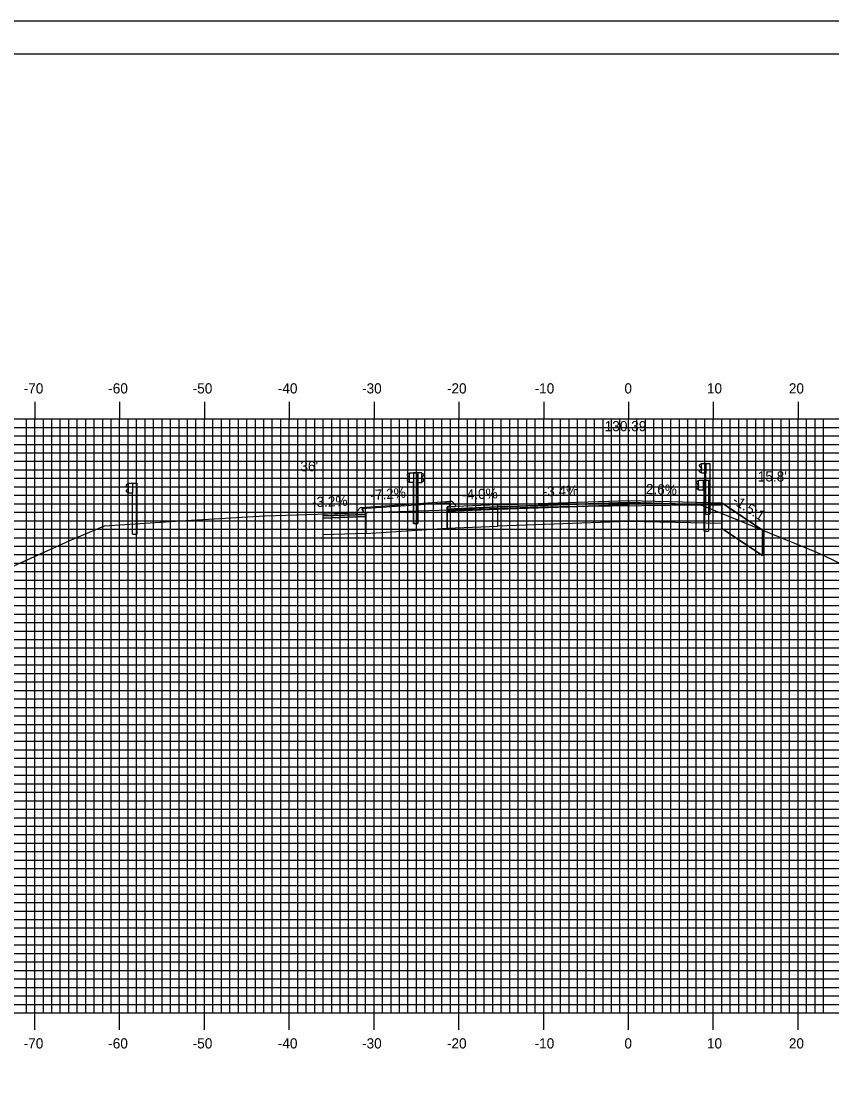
# Model space of a CAD drawing. Extents: x 859078 to 859421, y 364765 to 364985.
# Drawn here: x 859171.7 to 859267.3, y 364860.7 to 364985.2 of the extents above; entities that cross this region are included whole.
import ezdxf

# ---------------------------------------------------------------- set-up
doc = ezdxf.new("R2010")
doc.units = 0
for name, color, linetype in [('ANNOTATION', 7, 'Continuous'), ('BORDER', 7, 'Continuous'), ('D_Curb_Type_3M2_Lt', 7, 'Continuous'), ('D_Curb_Type_3M2_Rt', 7, 'Continuous'), ('D_Guardrail_Beam_Rt', 7, 'Continuous'), ('D_Roadway_Centerline_Text', 7, 'Continuous'), ('D_Roadway_Edge_Shoulder', 7, 'Continuous'), ('D_Roadway_Edge_TW', 7, 'Continuous'), ('D_Roadway_FinishedGrade', 7, 'Continuous'), ('D_Roadway_Pavement', 7, 'Continuous'), ('D_Roadway_SubGrade', 7, 'Continuous'), ('D_Text_Standard', 7, 'Continuous'), ('H_V ANNOTATION', 7, 'Continuous'), ('M_Guardrail', 7, 'Continuous'), ('M_Roadway_Centerline', 7, 'Continuous'), ('MAJOR', 7, 'Continuous'), ('MINOR', 7, 'Continuous'), ('PATTERNING', 7, 'Continuous'), ('PLOT BOUNDARY', 7, 'Continuous'), ('S_Roadway_Centerline', 7, 'Continuous')]:
    doc.layers.add(name, color=color, linetype=linetype)

msp = doc.modelspace()

# ---------------------------------------------------------------- linework, layer by layer
at = {"layer": 'BORDER'}
msp.add_lwpolyline([(859093.76, 364771.3), (859413.76, 364771.3), (859413.76, 364981.3), (859093.76, 364981.3)], close=True, dxfattribs=at)
at = {"layer": 'D_Curb_Type_3M2_Lt'}
for p, q in [((859222.47, 364928.59), (859222.47, 364928.59)), ((859222.33, 364928.46), (859222.22, 364927.97)), ((859222.22, 364927.97), (859222.97, 364927.97)), ((859222.97, 364928.13), (859222.62, 364928.53)), ((859222.97, 364927.97), (859222.97, 364928.13))]:
    msp.add_line(p, q, dxfattribs=at)
msp.add_arc((859222.49, 364928.42), 0.167, 41.387, 167.6648, dxfattribs=at)
at = {"layer": 'D_Curb_Type_3M2_Rt'}
for p, q in [((859211.37, 364927.41), (859211.73, 364927.81)), ((859211.37, 364927.24), (859211.37, 364927.41)), ((859212.01, 364927.74), (859212.12, 364927.24)), ((859212.12, 364927.24), (859211.37, 364927.24))]:
    msp.add_line(p, q, dxfattribs=at)
msp.add_arc((859211.85, 364927.7), 0.167, 12.3352, 138.613, dxfattribs=at)
at = {"layer": 'D_Guardrail_Beam_Rt'}
for p, q in [((859251.63, 364931.06), (859252.32, 364931.06)), ((859251.63, 364929.89), (859251.63, 364931.06)), ((859252.15, 364931.06), (859252.15, 364929.89)), ((859252.26, 364931.06), (859252.26, 364929.89)), ((859252.32, 364931.06), (859252.79, 364931.06)), ((859252.32, 364931.06), (859252.32, 364929.89)), ((859252.79, 364931.06), (859252.79, 364925.06)), ((859251.54, 364930.96), (859251.4, 364930.86)), ((859251.4, 364930.71), (859251.59, 364930.58)), ((859251.59, 364930.38), (859251.4, 364930.24)), ((859251.4, 364930.1), (859251.54, 364930)), ((859251.63, 364930.98), (859251.56, 364930.96)), ((859251.56, 364929.99), (859251.63, 364929.98)), ((859251.63, 364930.51), (859251.63, 364930.44)), ((859252.32, 364929.89), (859251.63, 364929.89)), ((859252.3, 364925.06), (859252.3, 364929.89)), ((859252.3, 364925.06), (859252.79, 364925.06))]:
    msp.add_line(p, q, dxfattribs=at)
for centre, major_axis, start_param, end_param in [((859251.45, 364930.79), (-0.0877, 0), 5.323254, 7.243116), ((859251.45, 364930.17), (-0.0877, 0), 5.323254, 7.243116), ((859251.56, 364930.92), (-0.0417, 0), 4.907132, 5.323254), ((859251.56, 364930.03), (-0.0417, 0), 0.959931, 1.376053), ((859251.55, 364930.51), (0.0789, 0), 0, 0.959931), ((859251.55, 364930.44), (0.0789, 0), 5.323254, 6.283185)]:
    msp.add_ellipse(centre, major_axis=major_axis, ratio=0.995501, start_param=start_param, end_param=end_param, dxfattribs=at)
at = {"layer": 'D_Roadway_Edge_Shoulder'}
for points in [[(859243.36, 364928.69), (859251.36, 364928.48), (859251.36, 364928.48), (859254.36, 364928.4), (859254.36, 364928.15), (859243.36, 364928.44)], [(859227.97, 364928.17), (859222.97, 364927.97), (859221.97, 364927.93), (859221.97, 364927.68), (859227.97, 364927.92)], [(859207.37, 364927.12), (859211.37, 364927.24), (859212.37, 364927.28), (859212.37, 364927.03), (859207.37, 364926.87)]]:
    msp.add_lwpolyline(points, close=True, dxfattribs=at)
at = {"layer": 'D_Roadway_Edge_TW'}
msp.add_lwpolyline([(859227.97, 364928.17), (859243.36, 364928.69), (859243.36, 364928.44), (859227.97, 364927.92)], close=True, dxfattribs=at)
at = {"layer": 'D_Roadway_FinishedGrade'}
msp.add_line((859254.36, 364928.4), (859254.36, 364925.4), dxfattribs=at)
for points in [[(859211.89, 364927.86), (859222.45, 364928.59)], [(859254.36, 364928.4), (859255.86, 364927.4), (859259.16, 364925.2)], [(859259.16, 364925.2), (859259.16, 364922.2), (859254.36, 364925.4)]]:
    msp.add_lwpolyline(points, dxfattribs=at)
at = {"layer": 'D_Roadway_Pavement'}
for points in [[(859227.97, 364927.92), (859221.97, 364927.68), (859221.97, 364927.43), (859227.97, 364927.67)], [(859227.97, 364927.92), (859243.36, 364928.44), (859243.36, 364928.19), (859227.97, 364927.67)], [(859207.37, 364926.87), (859212.37, 364927.03), (859212.37, 364926.78), (859207.37, 364926.62)]]:
    msp.add_lwpolyline(points, close=True, dxfattribs=at)
msp.add_lwpolyline([(859243.36, 364928.44), (859243.36, 364928.19)], dxfattribs=at)
msp.add_lwpolyline([(859243.36, 364928.44), (859243.36, 364928.19)], dxfattribs=at)
at = {"layer": 'D_Roadway_SubGrade'}
for points in [[(859212.37, 364927.28), (859212.37, 364924.78), (859221.97, 364925.43), (859221.97, 364927.43), (859221.97, 364927.68), (859221.97, 364927.93), (859222.21, 364927.94), (859222.32, 364928.41), (859211.9, 364927.7), (859212.12, 364927.27)], [(859227.97, 364927.67), (859221.97, 364927.43), (859221.97, 364927.68), (859221.97, 364925.43), (859227.97, 364925.67)], [(859227.97, 364927.67), (859243.36, 364928.19), (859243.36, 364926.19), (859227.97, 364925.67)], [(859243.36, 364928.19), (859243.36, 364928.44), (859254.36, 364928.15), (859254.36, 364928.4), (859254.36, 364925.97), (859243.36, 364926.19)], [(859207.37, 364926.62), (859212.37, 364926.78), (859212.37, 364927.03), (859212.37, 364924.78), (859207.37, 364924.62)]]:
    msp.add_lwpolyline(points, close=True, dxfattribs=at)
at = {"layer": 'M_Guardrail'}
for p, q in [((859251.88, 364932.96), (859251.73, 364932.86)), ((859251.73, 364932.72), (859251.93, 364932.58)), ((859251.93, 364932.36), (859251.73, 364932.23)), ((859251.98, 364932.98), (859251.89, 364932.97)), ((859251.96, 364932.52), (859251.96, 364932.43)), ((859251.98, 364933.06), (859252.47, 364933.06)), ((859251.98, 364931.89), (859251.98, 364933.06)), ((859252.47, 364933.06), (859252.96, 364933.06)), ((859252.47, 364933.06), (859252.47, 364931.89)), ((859252.96, 364933.06), (859252.96, 364927.06)), ((859217.43, 364931.87), (859217.28, 364931.77)), ((859217.28, 364931.63), (859217.48, 364931.49)), ((859217.48, 364931.27), (859217.28, 364931.13)), ((859217.53, 364931.89), (859217.44, 364931.88)), ((859217.51, 364931.43), (859217.51, 364931.33)), ((859217.53, 364931.96), (859218.02, 364931.96)), ((859217.53, 364930.8), (859217.53, 364931.96)), ((859218, 364931.96), (859218, 364925.96)), ((859218.5, 364931.96), (859218, 364931.96)), ((859218.02, 364931.96), (859218.51, 364931.96)), ((859218.02, 364931.96), (859218.02, 364930.8)), ((859218.99, 364931.96), (859218.5, 364931.96)), ((859218.5, 364931.96), (859218.5, 364930.79)), ((859218.51, 364931.96), (859218.51, 364925.96)), ((859218.99, 364930.79), (859218.99, 364931.96)), ((859218.99, 364931.89), (859219.07, 364931.87)), ((859219, 364931.42), (859219, 364931.33)), ((859219.23, 364931.62), (859219.03, 364931.49)), ((859219.03, 364931.27), (859219.23, 364931.13)), ((859219.08, 364931.87), (859219.23, 364931.77)), ((859251.73, 364932.08), (859251.88, 364931.98)), ((859251.89, 364931.98), (859251.98, 364931.96)), ((859252.47, 364931.89), (859251.98, 364931.89)), ((859252.47, 364927.06), (859252.47, 364931.89)), ((859184.3, 364930.62), (859184.16, 364930.52)), ((859184.16, 364930.38), (859184.35, 364930.24)), ((859184.35, 364930.02), (859184.16, 364929.89)), ((859184.4, 364930.64), (859184.32, 364930.63)), ((859184.38, 364930.18), (859184.38, 364930.09)), ((859184.4, 364930.72), (859184.89, 364930.72)), ((859184.4, 364929.55), (859184.4, 364930.72)), ((859184.89, 364930.72), (859185.38, 364930.72)), ((859184.89, 364930.72), (859184.89, 364929.55)), ((859185.38, 364930.72), (859185.38, 364924.72)), ((859217.28, 364930.99), (859217.43, 364930.89)), ((859217.44, 364930.88), (859217.53, 364930.87)), ((859218.02, 364930.8), (859217.53, 364930.8)), ((859218.02, 364925.96), (859218.02, 364930.8)), ((859218.5, 364925.96), (859218.5, 364930.79)), ((859218.5, 364930.79), (859218.99, 364930.79)), ((859219.07, 364930.88), (859218.99, 364930.87)), ((859219.23, 364930.99), (859219.08, 364930.89)), ((859184.16, 364929.74), (859184.3, 364929.64)), ((859184.32, 364929.64), (859184.4, 364929.62)), ((859184.89, 364929.55), (859184.4, 364929.55)), ((859184.89, 364924.72), (859184.89, 364929.55)), ((859252.47, 364927.06), (859252.96, 364927.06)), ((859218.5, 364925.96), (859218, 364925.96)), ((859218.02, 364925.96), (859218.51, 364925.96)), ((859184.89, 364924.72), (859185.38, 364924.72))]:
    msp.add_line(p, q, dxfattribs=at)
for centre, major_axis, start_param, end_param in [((859251.78, 364932.79), (-0.0877, 0), 5.323254, 7.243116), ((859251.9, 364932.93), (-0.0417, 0), 4.886922, 5.323254), ((859251.88, 364932.52), (0.0789, 0), 0, 0.959931), ((859251.88, 364932.43), (0.0789, 0), 5.323254, 6.283185), ((859217.34, 364931.7), (-0.0877, 0), 5.323254, 7.243116), ((859217.34, 364931.06), (-0.0877, 0), 5.323254, 7.243116), ((859217.45, 364931.84), (-0.0417, 0), 4.886922, 5.323254), ((859217.43, 364931.43), (0.0789, 0), 0, 0.959931), ((859217.43, 364931.33), (0.0789, 0), 5.323254, 6.283185), ((859219.08, 364931.42), (-0.0789, 0), 5.323254, 6.283185), ((859219.08, 364931.33), (-0.0789, 0), 6.283185, 7.243116), ((859219.06, 364931.83), (0.0417, 0), 0.959931, 1.396263), ((859219.18, 364931.69), (0.0877, 0), 5.323254, 7.243116), ((859219.18, 364931.06), (0.0877, 0), 5.323254, 7.243116), ((859251.78, 364932.15), (-0.0877, 0), 5.323254, 7.243116), ((859251.9, 364932.02), (-0.0417, 0), 0.959931, 1.396263), ((859184.21, 364930.45), (-0.0877, 0), 5.323254, 7.243116), ((859184.21, 364929.82), (-0.0877, 0), 5.323254, 7.243116), ((859184.32, 364930.59), (-0.0417, 0), 4.886922, 5.323254), ((859184.31, 364930.18), (0.0789, 0), 0, 0.959931), ((859184.31, 364930.09), (0.0789, 0), 5.323254, 6.283185), ((859217.45, 364930.93), (-0.0417, 0), 0.959931, 1.396263), ((859219.06, 364930.92), (0.0417, 0), 4.886922, 5.323254), ((859184.32, 364929.68), (-0.0417, 0), 0.959931, 1.396263)]:
    msp.add_ellipse(centre, major_axis=major_axis, ratio=0.995501, start_param=start_param, end_param=end_param, dxfattribs=at)
at = {"layer": 'MAJOR'}
for p, q in [((859173.36, 364940.31), (859173.36, 364938.3)), ((859183.36, 364940.31), (859183.36, 364938.3)), ((859193.36, 364940.31), (859193.36, 364938.3)), ((859203.36, 364940.31), (859203.36, 364938.3)), ((859213.36, 364940.31), (859213.36, 364938.3)), ((859223.36, 364940.31), (859223.36, 364938.3)), ((859233.36, 364940.31), (859233.36, 364938.3)), ((859243.36, 364940.31), (859243.36, 364938.3)), ((859253.36, 364940.31), (859253.36, 364938.3)), ((859263.36, 364940.31), (859263.36, 364938.3)), ((859103.36, 364938.3), (859383.36, 364938.3)), ((859103.36, 364938.3), (859383.36, 364938.3)), ((859173.36, 364868.3), (859173.36, 364938.3)), ((859183.36, 364868.3), (859183.36, 364938.3)), ((859193.36, 364868.3), (859193.36, 364938.3)), ((859203.36, 364868.3), (859203.36, 364938.3)), ((859213.36, 364868.3), (859213.36, 364938.3)), ((859223.36, 364868.3), (859223.36, 364938.3)), ((859233.36, 364868.3), (859233.36, 364938.3)), ((859243.36, 364868.3), (859243.36, 364938.3)), ((859253.36, 364868.3), (859253.36, 364938.3)), ((859263.36, 364868.3), (859263.36, 364938.3)), ((859103.36, 364933.3), (859383.36, 364933.3)), ((859103.36, 364928.3), (859383.36, 364928.3)), ((859103.36, 364923.3), (859383.36, 364923.3)), ((859103.36, 364918.3), (859383.36, 364918.3)), ((859103.36, 364913.3), (859383.36, 364913.3)), ((859103.36, 364908.3), (859383.36, 364908.3)), ((859103.36, 364903.3), (859383.36, 364903.3)), ((859103.36, 364898.3), (859383.36, 364898.3)), ((859103.36, 364893.3), (859383.36, 364893.3)), ((859103.36, 364888.3), (859383.36, 364888.3)), ((859103.36, 364883.3), (859383.36, 364883.3)), ((859103.36, 364878.3), (859383.36, 364878.3)), ((859103.36, 364873.3), (859383.36, 364873.3)), ((859103.36, 364868.3), (859383.36, 364868.3)), ((859103.36, 364868.3), (859383.36, 364868.3)), ((859173.36, 364866.3), (859173.36, 364868.3)), ((859183.36, 364866.3), (859183.36, 364868.3)), ((859193.36, 364866.3), (859193.36, 364868.3)), ((859203.36, 364866.3), (859203.36, 364868.3)), ((859213.36, 364866.3), (859213.36, 364868.3)), ((859223.36, 364866.3), (859223.36, 364868.3)), ((859233.36, 364866.3), (859233.36, 364868.3)), ((859243.36, 364866.3), (859243.36, 364868.3)), ((859253.36, 364866.3), (859253.36, 364868.3)), ((859263.36, 364866.3), (859263.36, 364868.3))]:
    msp.add_line(p, q, dxfattribs=at)
at = {"layer": 'MINOR'}
for p, q in [((859103.36, 364937.3), (859383.36, 364937.3)), ((859172.36, 364868.3), (859172.36, 364938.3)), ((859174.36, 364868.3), (859174.36, 364938.3)), ((859175.36, 364868.3), (859175.36, 364938.3)), ((859176.36, 364868.3), (859176.36, 364938.3)), ((859177.36, 364868.3), (859177.36, 364938.3)), ((859178.36, 364868.3), (859178.36, 364938.3)), ((859179.36, 364868.3), (859179.36, 364938.3)), ((859180.36, 364868.3), (859180.36, 364938.3)), ((859181.36, 364868.3), (859181.36, 364938.3)), ((859182.36, 364868.3), (859182.36, 364938.3)), ((859184.36, 364868.3), (859184.36, 364938.3)), ((859185.36, 364868.3), (859185.36, 364938.3)), ((859186.36, 364868.3), (859186.36, 364938.3)), ((859187.36, 364868.3), (859187.36, 364938.3)), ((859188.36, 364868.3), (859188.36, 364938.3)), ((859189.36, 364868.3), (859189.36, 364938.3)), ((859190.36, 364868.3), (859190.36, 364938.3)), ((859191.36, 364868.3), (859191.36, 364938.3)), ((859192.36, 364868.3), (859192.36, 364938.3)), ((859194.36, 364868.3), (859194.36, 364938.3)), ((859195.36, 364868.3), (859195.36, 364938.3)), ((859196.36, 364868.3), (859196.36, 364938.3)), ((859197.36, 364868.3), (859197.36, 364938.3)), ((859198.36, 364868.3), (859198.36, 364938.3)), ((859199.36, 364868.3), (859199.36, 364938.3)), ((859200.36, 364868.3), (859200.36, 364938.3)), ((859201.36, 364868.3), (859201.36, 364938.3)), ((859202.36, 364868.3), (859202.36, 364938.3)), ((859204.36, 364868.3), (859204.36, 364938.3)), ((859205.36, 364868.3), (859205.36, 364938.3)), ((859206.36, 364868.3), (859206.36, 364938.3)), ((859207.36, 364868.3), (859207.36, 364938.3)), ((859208.36, 364868.3), (859208.36, 364938.3)), ((859209.36, 364868.3), (859209.36, 364938.3)), ((859210.36, 364868.3), (859210.36, 364938.3)), ((859211.36, 364868.3), (859211.36, 364938.3)), ((859212.36, 364868.3), (859212.36, 364938.3)), ((859214.36, 364868.3), (859214.36, 364938.3)), ((859215.36, 364868.3), (859215.36, 364938.3)), ((859216.36, 364868.3), (859216.36, 364938.3)), ((859217.36, 364868.3), (859217.36, 364938.3)), ((859218.36, 364868.3), (859218.36, 364938.3)), ((859219.36, 364868.3), (859219.36, 364938.3)), ((859220.36, 364868.3), (859220.36, 364938.3)), ((859221.36, 364868.3), (859221.36, 364938.3)), ((859222.36, 364868.3), (859222.36, 364938.3)), ((859224.36, 364868.3), (859224.36, 364938.3)), ((859225.36, 364868.3), (859225.36, 364938.3)), ((859226.36, 364868.3), (859226.36, 364938.3)), ((859227.36, 364868.3), (859227.36, 364938.3)), ((859228.36, 364868.3), (859228.36, 364938.3)), ((859229.36, 364868.3), (859229.36, 364938.3)), ((859230.36, 364868.3), (859230.36, 364938.3)), ((859231.36, 364868.3), (859231.36, 364938.3)), ((859232.36, 364868.3), (859232.36, 364938.3)), ((859234.36, 364868.3), (859234.36, 364938.3)), ((859235.36, 364868.3), (859235.36, 364938.3)), ((859236.36, 364868.3), (859236.36, 364938.3)), ((859237.36, 364868.3), (859237.36, 364938.3)), ((859238.36, 364868.3), (859238.36, 364938.3)), ((859239.36, 364868.3), (859239.36, 364938.3)), ((859240.36, 364868.3), (859240.36, 364938.3)), ((859241.36, 364868.3), (859241.36, 364938.3)), ((859242.36, 364868.3), (859242.36, 364938.3)), ((859244.36, 364868.3), (859244.36, 364938.3)), ((859245.36, 364868.3), (859245.36, 364938.3)), ((859246.36, 364868.3), (859246.36, 364938.3)), ((859247.36, 364868.3), (859247.36, 364938.3)), ((859248.36, 364868.3), (859248.36, 364938.3)), ((859249.36, 364868.3), (859249.36, 364938.3)), ((859250.36, 364868.3), (859250.36, 364938.3)), ((859251.36, 364868.3), (859251.36, 364938.3)), ((859252.36, 364868.3), (859252.36, 364938.3)), ((859254.36, 364868.3), (859254.36, 364938.3)), ((859255.36, 364868.3), (859255.36, 364938.3)), ((859256.36, 364868.3), (859256.36, 364938.3)), ((859257.36, 364868.3), (859257.36, 364938.3)), ((859258.36, 364868.3), (859258.36, 364938.3)), ((859259.36, 364868.3), (859259.36, 364938.3)), ((859260.36, 364868.3), (859260.36, 364938.3)), ((859261.36, 364868.3), (859261.36, 364938.3)), ((859262.36, 364868.3), (859262.36, 364938.3)), ((859264.36, 364868.3), (859264.36, 364938.3)), ((859265.36, 364868.3), (859265.36, 364938.3)), ((859266.36, 364868.3), (859266.36, 364938.3)), ((859103.36, 364936.3), (859383.36, 364936.3)), ((859103.36, 364935.3), (859383.36, 364935.3)), ((859103.36, 364934.3), (859383.36, 364934.3)), ((859103.36, 364932.3), (859383.36, 364932.3)), ((859103.36, 364931.3), (859383.36, 364931.3)), ((859103.36, 364930.3), (859383.36, 364930.3)), ((859103.36, 364929.3), (859383.36, 364929.3)), ((859103.36, 364927.3), (859383.36, 364927.3)), ((859103.36, 364926.3), (859383.36, 364926.3)), ((859103.36, 364925.3), (859383.36, 364925.3)), ((859103.36, 364924.3), (859383.36, 364924.3)), ((859103.36, 364922.3), (859383.36, 364922.3)), ((859103.36, 364921.3), (859383.36, 364921.3)), ((859103.36, 364920.3), (859383.36, 364920.3)), ((859103.36, 364919.3), (859383.36, 364919.3)), ((859103.36, 364917.3), (859383.36, 364917.3)), ((859103.36, 364916.3), (859383.36, 364916.3)), ((859103.36, 364915.3), (859383.36, 364915.3)), ((859103.36, 364914.3), (859383.36, 364914.3)), ((859103.36, 364912.3), (859383.36, 364912.3)), ((859103.36, 364911.3), (859383.36, 364911.3)), ((859103.36, 364910.3), (859383.36, 364910.3)), ((859103.36, 364909.3), (859383.36, 364909.3)), ((859103.36, 364907.3), (859383.36, 364907.3)), ((859103.36, 364906.3), (859383.36, 364906.3)), ((859103.36, 364905.3), (859383.36, 364905.3)), ((859103.36, 364904.3), (859383.36, 364904.3)), ((859103.36, 364902.3), (859383.36, 364902.3)), ((859103.36, 364901.3), (859383.36, 364901.3)), ((859103.36, 364900.3), (859383.36, 364900.3)), ((859103.36, 364899.3), (859383.36, 364899.3)), ((859103.36, 364897.3), (859383.36, 364897.3)), ((859103.36, 364896.3), (859383.36, 364896.3)), ((859103.36, 364895.3), (859383.36, 364895.3)), ((859103.36, 364894.3), (859383.36, 364894.3)), ((859103.36, 364892.3), (859383.36, 364892.3)), ((859103.36, 364891.3), (859383.36, 364891.3)), ((859103.36, 364890.3), (859383.36, 364890.3)), ((859103.36, 364889.3), (859383.36, 364889.3)), ((859103.36, 364887.3), (859383.36, 364887.3)), ((859103.36, 364886.3), (859383.36, 364886.3)), ((859103.36, 364885.3), (859383.36, 364885.3)), ((859103.36, 364884.3), (859383.36, 364884.3)), ((859103.36, 364882.3), (859383.36, 364882.3)), ((859103.36, 364881.3), (859383.36, 364881.3)), ((859103.36, 364880.3), (859383.36, 364880.3)), ((859103.36, 364879.3), (859383.36, 364879.3)), ((859103.36, 364877.3), (859383.36, 364877.3)), ((859103.36, 364876.3), (859383.36, 364876.3)), ((859103.36, 364875.3), (859383.36, 364875.3)), ((859103.36, 364874.3), (859383.36, 364874.3)), ((859103.36, 364872.3), (859383.36, 364872.3)), ((859103.36, 364871.3), (859383.36, 364871.3)), ((859103.36, 364870.3), (859383.36, 364870.3)), ((859103.36, 364869.3), (859383.36, 364869.3))]:
    msp.add_line(p, q, dxfattribs=at)
at = {"layer": 'PATTERNING'}
msp.add_lwpolyline([(859254.36, 364928.4), (859254.36, 364925.4), (859259.18, 364922.19), (859259.16, 364925.2)], close=True, dxfattribs=at)
at = {"layer": 'PLOT BOUNDARY'}
msp.add_lwpolyline([(859077.57, 364765.18), (859417.57, 364765.18), (859417.57, 364985.18), (859077.57, 364985.18)], close=True, dxfattribs=at)
at = {"layer": 'S_Roadway_Centerline'}
msp.add_lwpolyline([(859103.36, 364902.01), (859121.41, 364901.16), (859123.7, 364901.17), (859140.77, 364906.69), (859146.96, 364909.28), (859161.1, 364916.57), (859177.76, 364924.08), (859181.57, 364925.69), (859191.17, 364926.32), (859200.46, 364926.88), (859206.7, 364927.09), (859232.95, 364927.94), (859237.94, 364928.01), (859251.9, 364928.18), (859265.53, 364922.58), (859267.32, 364921.76), (859278.31, 364916.2)], dxfattribs=at)

# ---------------------------------------------------------------- texts
at = {"layer": 'ANNOTATION'}
for s, rotation, p in [('-7.2%', 4.1369, (859212.96, 364928.71)), ('-4.0%', 2.2904, (859223.77, 364928.77)), ('-3.4%', 1.9427, (859233.26, 364929.15)), ('2.6%', 358.4963, (859245.4, 364929.44)), ('-3.2%', 1.8491, (859206.06, 364927.9)), ('-1.5:1', 327.8812, (859255.5, 364928.41))]:
    msp.add_text(s, height=1.2, rotation=rotation, dxfattribs=at).set_placement(p)
at = {"layer": 'D_Roadway_Centerline_Text'}
msp.add_text('130.39', height=1.2, dxfattribs=at).set_placement((859240.56, 364936.85))
at = {"layer": 'D_Text_Standard'}
for s, p in [("36'", (859204.66, 364932.13)), ("15.8'", (859258.61, 364930.92))]:
    msp.add_text(s, height=1.2, dxfattribs=at).set_placement(p)
at = {"layer": 'H_V ANNOTATION'}
for s, p in [('-70', (859172.04, 364941.3)), ('-60', (859182.01, 364941.3)), ('-50', (859191.97, 364941.3)), ('-40', (859202.01, 364941.3)), ('-30', (859211.94, 364941.3)), ('-20', (859221.95, 364941.3)), ('-10', (859232.29, 364941.3)), ('0', (859242.88, 364941.3)), ('10', (859252.61, 364941.3)), ('20', (859262.27, 364941.3)), ('-70', (859172.04, 364864.1)), ('-60', (859182.01, 364864.1)), ('-50', (859191.97, 364864.1)), ('-40', (859202.01, 364864.1)), ('-30', (859211.94, 364864.1)), ('-20', (859221.95, 364864.1)), ('-10', (859232.29, 364864.1)), ('0', (859242.88, 364864.1)), ('10', (859252.61, 364864.1)), ('20', (859262.27, 364864.1))]:
    msp.add_text(s, height=1.2, dxfattribs=at).set_placement(p)
at = {"layer": 'M_Roadway_Centerline'}
for s, p in [('C', (859232.95, 364927.94)), ('L', (859232.95, 364927.93)), ('C', (859200.46, 364926.88)), ('L', (859200.46, 364926.87))]:
    msp.add_text(s, height=0.0146, dxfattribs=at).set_placement(p)

doc.saveas('drawing.dxf')
